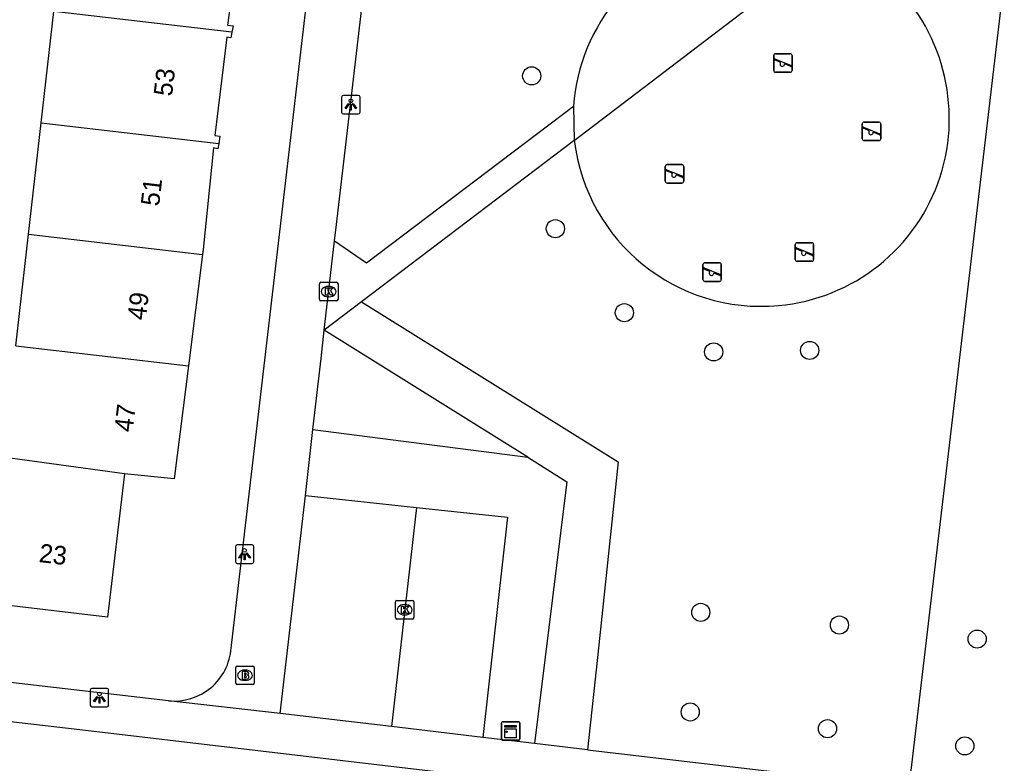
# Model space of a CAD drawing. Extents: x 161243 to 161752, y 384138 to 384885.
# Drawn here: x 161379.5 to 161432.8, y 384429.2 to 384469.3 of the extents above; entities that cross this region are included whole.
import ezdxf

# ---------------------------------------------------------------- set-up
doc = ezdxf.new("R2010")
doc.units = 0
for name, color, linetype in [('IMGEO_Boom', 7, 'Continuous'), ('IMGEO_Brandkraan', 7, 'Continuous'), ('IMGEO_Groenvoorziening', 7, 'Continuous'), ('IMGEO_Kast', 7, 'Continuous'), ('IMGEO_Kolk', 7, 'Continuous'), ('IMGEO_Lichtpunt', 7, 'Continuous'), ('IMGEO_Pand', 7, 'Continuous'), ('IMGEO_Pand_nummerreeks', 7, 'Continuous'), ('IMGEO_Parkeervlak_open', 7, 'Continuous'), ('IMGEO_Rijbaan_lokaal_open', 7, 'Continuous'), ('IMGEO_Speelvoorziening', 7, 'Continuous'), ('IMGEO_Voetpad_open', 7, 'Continuous')]:
    doc.layers.add(name, color=color, linetype=linetype)

msp = doc.modelspace()

# ---------------------------------------------------------------- linework, layer by layer
at = {"layer": 'IMGEO_Boom'}
for centre in [(161407.08, 384466.268), (161408.358, 384458.028), (161412.078, 384453.5), (161416.893, 384451.385), (161422.071, 384451.466), (161416.198, 384437.343), (161423.675, 384436.66), (161431.104, 384435.903), (161415.63, 384431.973), (161423.034, 384431.071), (161430.439, 384430.143)]:
    msp.add_circle(centre, 0.489, dxfattribs=at)
at = {"layer": 'IMGEO_Brandkraan'}
for p, q in [((161391.117, 384433.524), (161391.117, 384434.376)), ((161391.192, 384434.45), (161392.044, 384434.45)), ((161391.605, 384434.23), (161391.63, 384434.23)), ((161392.118, 384434.376), (161392.118, 384433.524)), ((161391.628, 384433.67), (161391.603, 384433.67)), ((161392.044, 384433.45), (161391.192, 384433.45))]:
    msp.add_line(p, q, dxfattribs=at)
for points in [[(161391.117, 384433.524), (161391.117, 384434.376)], [(161391.192, 384434.45), (161392.044, 384434.45)], [(161392.118, 384434.376), (161392.118, 384433.524)], [(161391.465, 384434.15), (161391.465, 384433.75), (161391.678, 384433.75)], [(161391.696, 384434.15), (161391.465, 384434.15)], [(161391.644, 384434.069), (161391.59, 384434.069), (161391.59, 384433.993)], [(161391.59, 384433.993), (161391.643, 384433.993)], [(161391.652, 384433.917), (161391.59, 384433.917), (161391.59, 384433.836)], [(161391.59, 384433.836), (161391.652, 384433.836)], [(161392.044, 384433.45), (161391.192, 384433.45)]]:
    msp.add_lwpolyline(points, dxfattribs=at)
for centre, radius, start, end in [((161391.194, 384434.374), 0.0765, 91.552, 178.448), ((161391.194, 384434.374), 0.0765, 91.552, 178.448), ((161392.042, 384434.374), 0.0765, 1.552, 88.448), ((161392.042, 384434.374), 0.0765, 1.552, 88.448), ((161391.645, 384434.031), 0.0379, 267.8285, 90.9355), ((161391.653, 384433.876), 0.0404, 269.8759, 90.5077), ((161391.684, 384434.001), 0.251, 268.6676, 293.5347), ((161391.7, 384434.005), 0.145, 59.4692, 91.5367), ((161391.725, 384434.052), 0.0922, 285.5137, 58.1501), ((161391.73, 384433.86), 0.105, 301.3115, 78.989), ((161391.194, 384433.526), 0.0765, 181.552, 268.448), ((161391.194, 384433.526), 0.0765, 181.552, 268.448), ((161392.042, 384433.526), 0.0765, 271.552, 358.448), ((161392.042, 384433.526), 0.0765, 271.552, 358.448)]:
    msp.add_arc(centre, radius, start, end, dxfattribs=at)
for centre, major_axis, ratio, start_param, end_param in [((161391.604, 384433.95), (-0.387, 0.002), 0.722429, 4.712389, 7.853982), ((161391.629, 384433.95), (-0.39, 0.002), 0.717154, 1.570796, 4.712389)]:
    msp.add_ellipse(centre, major_axis=major_axis, ratio=ratio, start_param=start_param, end_param=end_param, dxfattribs=at)
at = {"layer": 'IMGEO_Groenvoorziening'}
for points in [[(161427.439, 384427.904), (161432.833, 384473.658)], [(161397.9, 384454.084), (161411.738, 384445.455), (161410.62, 384434.912), (161410.092, 384429.939)], [(161406.866, 384445.708), (161395.896, 384452.566)], [(161395.284, 384447.211), (161406.866, 384445.708)], [(161406.866, 384445.708), (161408.983, 384444.384), (161407.225, 384430.276)]]:
    msp.add_lwpolyline(points, dxfattribs=at)
for centre, radius, start, end in [((161419.348, 384463.959), 10.255, 342.2151, 47.5938), ((161419.463, 384464.004), 10.16, 186.9303, 275.2343), ((161419.484, 384463.977), 10.132, 275.1329, 341.8865)]:
    msp.add_arc(centre, radius, start, end, dxfattribs=at)
at = {"layer": 'IMGEO_Kast'}
for p, q in [((161405.445, 384430.52), (161405.445, 384431.361)), ((161405.445, 384431.361), (161405.445, 384430.52)), ((161405.52, 384431.445), (161406.361, 384431.445)), ((161406.361, 384431.445), (161405.52, 384431.445)), ((161406.445, 384431.37), (161406.445, 384430.529)), ((161406.445, 384430.529), (161406.445, 384431.37)), ((161406.37, 384430.445), (161405.529, 384430.445)), ((161405.529, 384430.445), (161406.37, 384430.445))]:
    msp.add_line(p, q, dxfattribs=at)
for points in [[(161405.64, 384431.235), (161406.24, 384431.235), (161406.24, 384431.15), (161405.64, 384431.15), (161405.64, 384431.235)], [(161405.64, 384431.06), (161406.24, 384431.06), (161406.24, 384430.571), (161405.64, 384430.571), (161405.64, 384431.06)]]:
    msp.add_lwpolyline(points, dxfattribs=at)
msp.add_circle((161405.724, 384430.909), 0.0377, dxfattribs=at)
for centre, start, end in [((161405.523, 384431.367), 92.4484, 184.2845), ((161405.523, 384431.367), 92.4484, 184.2845), ((161406.367, 384431.367), 2.4484, 94.2845), ((161406.367, 384431.367), 2.4484, 94.2845), ((161405.523, 384430.523), 182.4484, 274.2845), ((161405.523, 384430.523), 182.4484, 274.2845), ((161406.367, 384430.523), 272.4484, 4.2845), ((161406.367, 384430.523), 272.4484, 4.2845)]:
    msp.add_arc(centre, 0.0779, start, end, dxfattribs=at)
at = {"layer": 'IMGEO_Kolk'}
for p, q in [((161395.633, 384454.213), (161395.633, 384455.065)), ((161395.708, 384455.139), (161396.56, 384455.139)), ((161396.634, 384455.065), (161396.634, 384454.213)), ((161396.121, 384454.919), (161396.146, 384454.919)), ((161396.56, 384454.139), (161395.708, 384454.139)), ((161396.144, 384454.359), (161396.119, 384454.359)), ((161399.73, 384437.058), (161399.73, 384437.91)), ((161399.805, 384437.984), (161400.657, 384437.984)), ((161400.731, 384437.91), (161400.731, 384437.058)), ((161400.218, 384437.764), (161400.243, 384437.764)), ((161400.657, 384436.984), (161399.805, 384436.984)), ((161400.241, 384437.204), (161400.216, 384437.204))]:
    msp.add_line(p, q, dxfattribs=at)
for points in [[(161395.633, 384454.213), (161395.633, 384455.065)], [(161395.708, 384455.139), (161396.56, 384455.139)], [(161396.634, 384455.065), (161396.634, 384454.213)], [(161395.954, 384454.839), (161396.077, 384454.839), (161396.077, 384454.688), (161396.207, 384454.839), (161396.371, 384454.839), (161396.225, 384454.688), (161396.378, 384454.439), (161396.226, 384454.439), (161396.141, 384454.603), (161396.077, 384454.536), (161396.077, 384454.439), (161395.954, 384454.439), (161395.954, 384454.839)], [(161396.56, 384454.139), (161395.708, 384454.139)], [(161399.73, 384437.058), (161399.73, 384437.91)], [(161399.805, 384437.984), (161400.657, 384437.984)], [(161400.731, 384437.91), (161400.731, 384437.058)], [(161400.051, 384437.684), (161400.174, 384437.684), (161400.174, 384437.533), (161400.304, 384437.684), (161400.468, 384437.684), (161400.322, 384437.533), (161400.475, 384437.284), (161400.323, 384437.284), (161400.238, 384437.448), (161400.174, 384437.381), (161400.174, 384437.284), (161400.051, 384437.284), (161400.051, 384437.684)], [(161400.657, 384436.984), (161399.805, 384436.984)]]:
    msp.add_lwpolyline(points, dxfattribs=at)
for centre, start, end in [((161395.71, 384455.063), 91.552, 178.448), ((161395.71, 384455.063), 91.552, 178.448), ((161396.558, 384455.063), 1.552, 88.448), ((161396.558, 384455.063), 1.552, 88.448), ((161395.71, 384454.215), 181.552, 268.448), ((161395.71, 384454.215), 181.552, 268.448), ((161396.558, 384454.215), 271.552, 358.448), ((161396.558, 384454.215), 271.552, 358.448), ((161399.807, 384437.908), 91.552, 178.448), ((161399.807, 384437.908), 91.552, 178.448), ((161400.655, 384437.908), 1.552, 88.448), ((161400.655, 384437.908), 1.552, 88.448), ((161399.807, 384437.06), 181.552, 268.448), ((161399.807, 384437.06), 181.552, 268.448), ((161400.655, 384437.06), 271.552, 358.448), ((161400.655, 384437.06), 271.552, 358.448)]:
    msp.add_arc(centre, 0.0765, start, end, dxfattribs=at)
for centre, major_axis, ratio, start_param, end_param in [((161396.12, 384454.639), (-0.387, 0.002), 0.722429, 4.712389, 7.853982), ((161396.145, 384454.639), (-0.39, 0.002), 0.717154, 1.570796, 4.712389), ((161400.217, 384437.484), (-0.387, 0.002), 0.722429, 4.712389, 7.853982), ((161400.242, 384437.484), (-0.39, 0.002), 0.717154, 1.570796, 4.712389)]:
    msp.add_ellipse(centre, major_axis=major_axis, ratio=ratio, start_param=start_param, end_param=end_param, dxfattribs=at)
at = {"layer": 'IMGEO_Lichtpunt'}
for p, q in [((161396.828, 384465.12), (161396.828, 384464.313)), ((161396.828, 384465.12), (161396.828, 384464.313)), ((161397.73, 384465.215), (161396.922, 384465.215)), ((161397.73, 384465.215), (161396.922, 384465.215)), ((161397.824, 384464.313), (161397.824, 384465.12)), ((161397.824, 384464.313), (161397.824, 384465.12)), ((161396.922, 384464.219), (161397.73, 384464.219)), ((161396.922, 384464.219), (161397.73, 384464.219)), ((161391.099, 384440.885), (161391.099, 384440.078)), ((161391.099, 384440.885), (161391.099, 384440.078)), ((161392.001, 384440.98), (161391.193, 384440.98)), ((161392.001, 384440.98), (161391.193, 384440.98)), ((161392.095, 384440.078), (161392.095, 384440.885)), ((161392.095, 384440.078), (161392.095, 384440.885)), ((161391.193, 384439.984), (161392.001, 384439.984)), ((161391.193, 384439.984), (161392.001, 384439.984)), ((161383.269, 384433.152), (161383.269, 384432.345)), ((161383.269, 384433.152), (161383.269, 384432.345)), ((161384.171, 384433.247), (161383.363, 384433.247)), ((161384.171, 384433.247), (161383.363, 384433.247)), ((161384.265, 384432.345), (161384.265, 384433.152)), ((161384.265, 384432.345), (161384.265, 384433.152)), ((161383.363, 384432.251), (161384.171, 384432.251)), ((161383.363, 384432.251), (161384.171, 384432.251))]:
    msp.add_line(p, q, dxfattribs=at)
for points in [[(161397.202, 384464.784), (161397.241, 384464.756), (161397.053, 384464.494), (161397.015, 384464.521), (161397.202, 384464.784)], [(161397.304, 384464.736), (161397.351, 384464.736), (161397.351, 384464.414), (161397.304, 384464.414), (161397.304, 384464.736)], [(161397.414, 384464.756), (161397.452, 384464.783), (161397.639, 384464.521), (161397.6, 384464.493), (161397.414, 384464.756)], [(161391.473, 384440.549), (161391.512, 384440.521), (161391.324, 384440.259), (161391.286, 384440.286), (161391.473, 384440.549)], [(161391.575, 384440.501), (161391.622, 384440.501), (161391.622, 384440.179), (161391.575, 384440.179), (161391.575, 384440.501)], [(161391.685, 384440.521), (161391.723, 384440.548), (161391.91, 384440.286), (161391.871, 384440.258), (161391.685, 384440.521)], [(161383.643, 384432.816), (161383.682, 384432.788), (161383.494, 384432.526), (161383.456, 384432.553), (161383.643, 384432.816)], [(161383.745, 384432.768), (161383.792, 384432.768), (161383.792, 384432.446), (161383.745, 384432.446), (161383.745, 384432.768)], [(161383.855, 384432.788), (161383.893, 384432.815), (161384.08, 384432.553), (161384.041, 384432.525), (161383.855, 384432.788)]]:
    msp.add_lwpolyline(points, dxfattribs=at)
for centre in [(161397.327, 384464.918), (161391.598, 384440.683), (161383.768, 384432.95)]:
    msp.add_circle(centre, 0.0994, dxfattribs=at)
for centre, start, end in [((161396.922, 384465.12), 90, 180), ((161396.922, 384465.12), 90, 180), ((161397.73, 384465.12), 0, 90), ((161397.73, 384465.12), 0, 90), ((161396.922, 384464.313), 180, 270), ((161396.922, 384464.313), 180, 270), ((161397.73, 384464.313), 270, 0), ((161397.73, 384464.313), 270, 360), ((161391.193, 384440.885), 90, 180), ((161391.193, 384440.885), 90, 180), ((161392.001, 384440.885), 0, 90), ((161392.001, 384440.885), 0, 90), ((161391.193, 384440.078), 180, 270), ((161391.193, 384440.078), 180, 270), ((161392.001, 384440.078), 270, 0), ((161392.001, 384440.078), 270, 360), ((161383.363, 384433.152), 90, 180), ((161383.363, 384433.152), 90, 180), ((161384.171, 384433.152), 0, 90), ((161384.171, 384433.152), 0, 90), ((161383.363, 384432.345), 180, 270), ((161383.363, 384432.345), 180, 270), ((161384.171, 384432.345), 270, 0), ((161384.171, 384432.345), 270, 360)]:
    msp.add_arc(centre, 0.0946, start, end, dxfattribs=at)
at = {"layer": 'IMGEO_Pand'}
for points in [[(161391.445, 384474.65), (161390.678, 384469.01), (161390.98, 384468.975), (161390.911, 384468.623)], [(161380.625, 384463.735), (161381.312, 384469.744)], [(161390.911, 384468.623), (161381.312, 384469.744)], [(161390.911, 384468.623), (161390.849, 384468.311), (161390.638, 384468.352), (161389.986, 384463.054), (161390.269, 384463.022), (161390.201, 384462.616)], [(161379.938, 384457.726), (161380.625, 384463.735)], [(161380.625, 384463.735), (161390.201, 384462.616)], [(161390.201, 384462.616), (161390.155, 384462.338), (161389.918, 384462.39), (161389.363, 384456.913), (161389.327, 384456.63)], [(161379.251, 384451.718), (161379.938, 384457.726)], [(161379.938, 384457.726), (161389.327, 384456.63)], [(161389.327, 384456.63), (161388.569, 384450.629)], [(161379.251, 384451.718), (161388.569, 384450.629)], [(161388.569, 384450.629), (161387.8, 384444.539), (161385.125, 384444.814)], [(161385.125, 384444.814), (161378.564, 384445.707)], [(161385.125, 384444.814), (161384.202, 384437.09), (161377.798, 384437.835), (161377.895, 384438.441)]]:
    msp.add_lwpolyline(points, dxfattribs=at)
at = {"layer": 'IMGEO_Parkeervlak_open'}
msp.add_lwpolyline([(161400.861, 384443.004), (161405.773, 384442.485), (161404.999, 384435.571), (161404.443, 384430.602)], dxfattribs=at)
at = {"layer": 'IMGEO_Rijbaan_lokaal_open'}
for points in [[(161393.511, 384431.885), (161394.875, 384443.637)], [(161394.875, 384443.637), (161400.861, 384443.004)], [(161400.861, 384443.004), (161399.514, 384431.19)], [(161336.535, 384438.485), (161336.257, 384436.376), (161382.402, 384431.06), (161401.922, 384428.768)], [(161399.514, 384431.19), (161393.511, 384431.885)]]:
    msp.add_lwpolyline(points, dxfattribs=at)
at = {"layer": 'IMGEO_Speelvoorziening'}
for p, q in [((161420.13, 384466.562), (161420.13, 384467.362)), ((161420.13, 384467.362), (161420.13, 384466.562)), ((161420.23, 384467.462), (161421.02, 384467.462)), ((161421.02, 384467.462), (161420.23, 384467.462)), ((161421.12, 384467.362), (161421.12, 384466.562)), ((161421.12, 384466.562), (161421.12, 384467.362)), ((161420.513, 384466.99), (161420.174, 384467.127)), ((161420.199, 384467.187), (161421.075, 384466.834)), ((161421.051, 384466.774), (161420.711, 384466.911)), ((161421.02, 384466.462), (161420.23, 384466.462)), ((161420.23, 384466.462), (161421.02, 384466.462)), ((161424.911, 384462.877), (161424.911, 384463.677)), ((161424.911, 384463.677), (161424.911, 384462.877)), ((161425.011, 384463.777), (161425.801, 384463.777)), ((161425.801, 384463.777), (161425.011, 384463.777)), ((161425.901, 384463.677), (161425.901, 384462.877)), ((161425.901, 384462.877), (161425.901, 384463.677)), ((161425.294, 384463.305), (161424.955, 384463.442)), ((161424.98, 384463.502), (161425.856, 384463.149)), ((161425.832, 384463.089), (161425.492, 384463.226)), ((161425.801, 384462.777), (161425.011, 384462.777)), ((161425.011, 384462.777), (161425.801, 384462.777)), ((161414.287, 384460.586), (161414.287, 384461.386)), ((161414.287, 384461.386), (161414.287, 384460.586)), ((161414.387, 384461.486), (161415.177, 384461.486)), ((161415.177, 384461.486), (161414.387, 384461.486)), ((161415.277, 384461.386), (161415.277, 384460.586)), ((161415.277, 384460.586), (161415.277, 384461.386)), ((161414.67, 384461.014), (161414.331, 384461.151)), ((161414.356, 384461.211), (161415.232, 384460.858)), ((161415.208, 384460.798), (161414.868, 384460.935)), ((161415.177, 384460.486), (161414.387, 384460.486)), ((161414.387, 384460.486), (161415.177, 384460.486)), ((161421.292, 384456.37), (161421.292, 384457.17)), ((161421.292, 384457.17), (161421.292, 384456.37)), ((161421.392, 384457.27), (161422.182, 384457.27)), ((161422.182, 384457.27), (161421.392, 384457.27)), ((161422.282, 384457.17), (161422.282, 384456.37)), ((161422.282, 384456.37), (161422.282, 384457.17)), ((161421.675, 384456.798), (161421.336, 384456.935)), ((161421.361, 384456.995), (161422.237, 384456.642)), ((161422.213, 384456.582), (161421.873, 384456.719)), ((161416.313, 384455.29), (161416.313, 384456.09)), ((161416.313, 384456.09), (161416.313, 384455.29)), ((161416.413, 384456.19), (161417.203, 384456.19)), ((161417.203, 384456.19), (161416.413, 384456.19)), ((161417.303, 384456.09), (161417.303, 384455.29)), ((161417.303, 384455.29), (161417.303, 384456.09)), ((161422.182, 384456.27), (161421.392, 384456.27)), ((161421.392, 384456.27), (161422.182, 384456.27)), ((161416.696, 384455.718), (161416.357, 384455.855)), ((161416.382, 384455.915), (161417.258, 384455.562)), ((161417.234, 384455.502), (161416.894, 384455.639)), ((161417.203, 384455.19), (161416.413, 384455.19)), ((161416.413, 384455.19), (161417.203, 384455.19))]:
    msp.add_line(p, q, dxfattribs=at)
for centre, radius, start, end in [((161420.23, 384467.362), 0.1, 90, 180), ((161420.23, 384467.362), 0.1, 90, 180), ((161421.02, 384467.362), 0.1, 0, 90), ((161421.02, 384467.362), 0.1, 360, 90), ((161420.187, 384467.157), 0.0327, 68.078, 248.078), ((161420.592, 384466.9), 0.12, 130.9928, 5.1632), ((161421.063, 384466.804), 0.0327, 248.078, 68.078), ((161420.23, 384466.562), 0.1, 180, 270), ((161420.23, 384466.562), 0.1, 180, 270), ((161421.02, 384466.562), 0.1, 270, 0), ((161421.02, 384466.562), 0.1, 270, 0), ((161425.011, 384463.677), 0.1, 90, 180), ((161425.011, 384463.677), 0.1, 90, 180), ((161425.801, 384463.677), 0.1, 0, 90), ((161425.801, 384463.677), 0.1, 360, 90), ((161424.968, 384463.472), 0.0327, 68.078, 248.078), ((161425.373, 384463.215), 0.12, 130.9928, 5.1632), ((161425.844, 384463.119), 0.0327, 248.078, 68.078), ((161425.011, 384462.877), 0.1, 180, 270), ((161425.011, 384462.877), 0.1, 180, 270), ((161425.801, 384462.877), 0.1, 270, 0), ((161425.801, 384462.877), 0.1, 270, 0), ((161414.387, 384461.386), 0.1, 90, 180), ((161414.387, 384461.386), 0.1, 90, 180), ((161415.177, 384461.386), 0.1, 0, 90), ((161415.177, 384461.386), 0.1, 360, 90), ((161414.344, 384461.181), 0.0327, 68.078, 248.078), ((161414.749, 384460.924), 0.12, 130.9928, 5.1632), ((161415.22, 384460.828), 0.0327, 248.078, 68.078), ((161414.387, 384460.586), 0.1, 180, 270), ((161414.387, 384460.586), 0.1, 180, 270), ((161415.177, 384460.586), 0.1, 270, 0), ((161415.177, 384460.586), 0.1, 270, 0), ((161421.392, 384457.17), 0.1, 90, 180), ((161421.392, 384457.17), 0.1, 90, 180), ((161422.182, 384457.17), 0.1, 0, 90), ((161422.182, 384457.17), 0.1, 360, 90), ((161421.349, 384456.965), 0.0327, 68.078, 248.078), ((161421.754, 384456.708), 0.12, 130.9928, 5.1632), ((161422.225, 384456.612), 0.0327, 248.078, 68.078), ((161416.413, 384456.09), 0.1, 90, 180), ((161416.413, 384456.09), 0.1, 90, 180), ((161417.203, 384456.09), 0.1, 0, 90), ((161417.203, 384456.09), 0.1, 360, 90), ((161421.392, 384456.37), 0.1, 180, 270), ((161421.392, 384456.37), 0.1, 180, 270), ((161422.182, 384456.37), 0.1, 270, 0), ((161422.182, 384456.37), 0.1, 270, 0), ((161416.37, 384455.885), 0.0327, 68.078, 248.078), ((161416.775, 384455.628), 0.12, 130.9928, 5.1632), ((161417.246, 384455.532), 0.0327, 248.078, 68.078), ((161416.413, 384455.29), 0.1, 180, 270), ((161416.413, 384455.29), 0.1, 180, 270), ((161417.203, 384455.29), 0.1, 270, 0), ((161417.203, 384455.29), 0.1, 270, 0)]:
    msp.add_arc(centre, radius, start, end, dxfattribs=at)
at = {"layer": 'IMGEO_Voetpad_open'}
for points in [[(161396.451, 384457.375), (161396.553, 384458.256), (161401.111, 384497.3)], [(161390.869, 384435.421), (161397.785, 384494.638)], [(161409.377, 384462.778), (161419.044, 384470.149)], [(161396.451, 384457.375), (161398.167, 384456.181), (161409.335, 384464.642)], [(161409.335, 384464.642), (161409.377, 384462.778)], [(161409.377, 384462.778), (161397.9, 384454.084)], [(161395.896, 384452.566), (161396.451, 384457.375)], [(161397.9, 384454.084), (161395.896, 384452.566)], [(161395.284, 384447.211), (161395.721, 384451.026), (161395.896, 384452.566)], [(161394.875, 384443.637), (161395.284, 384447.211)], [(161387.488, 384432.576), (161336.535, 384438.485)], [(161393.511, 384431.885), (161387.488, 384432.576)], [(161404.443, 384430.602), (161399.514, 384431.19)], [(161407.225, 384430.276), (161404.443, 384430.602)], [(161410.092, 384429.939), (161407.225, 384430.276)], [(161410.092, 384429.939), (161427.439, 384427.904)]]:
    msp.add_lwpolyline(points, dxfattribs=at)
for centre, radius, start, end in [((161419.354, 384463.937), 10.044, 139.0427, 175.9767), ((161387.796, 384435.641), 3.081, 264.2615, 355.8975)]:
    msp.add_arc(centre, radius, start, end, dxfattribs=at)

# ---------------------------------------------------------------- texts
at = {"layer": 'IMGEO_Pand_nummerreeks'}
for s, rotation, p in [('53', 83.3157, (161387.677, 384465.135)), ('51', 83.3157, (161386.983, 384459.211)), ('49', 83.3157, (161386.263, 384453.064)), ('47', 83.3157, (161385.555, 384447.029)), ('23', 353.3644, (161380.47, 384440.061))]:
    msp.add_text(s, height=1, rotation=rotation, dxfattribs=at).set_placement(p)

doc.saveas('drawing.dxf')
